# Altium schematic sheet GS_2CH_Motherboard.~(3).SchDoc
size A1; Dpartment: R&D; Date: 2024-10-27; DrawnBy: 杜龙彬; DocumentNumber: 2; Revision: V1.01; SheetNumber: 3; SheetTotal: 3; Model: 型号; Size: A1; Department: R&D
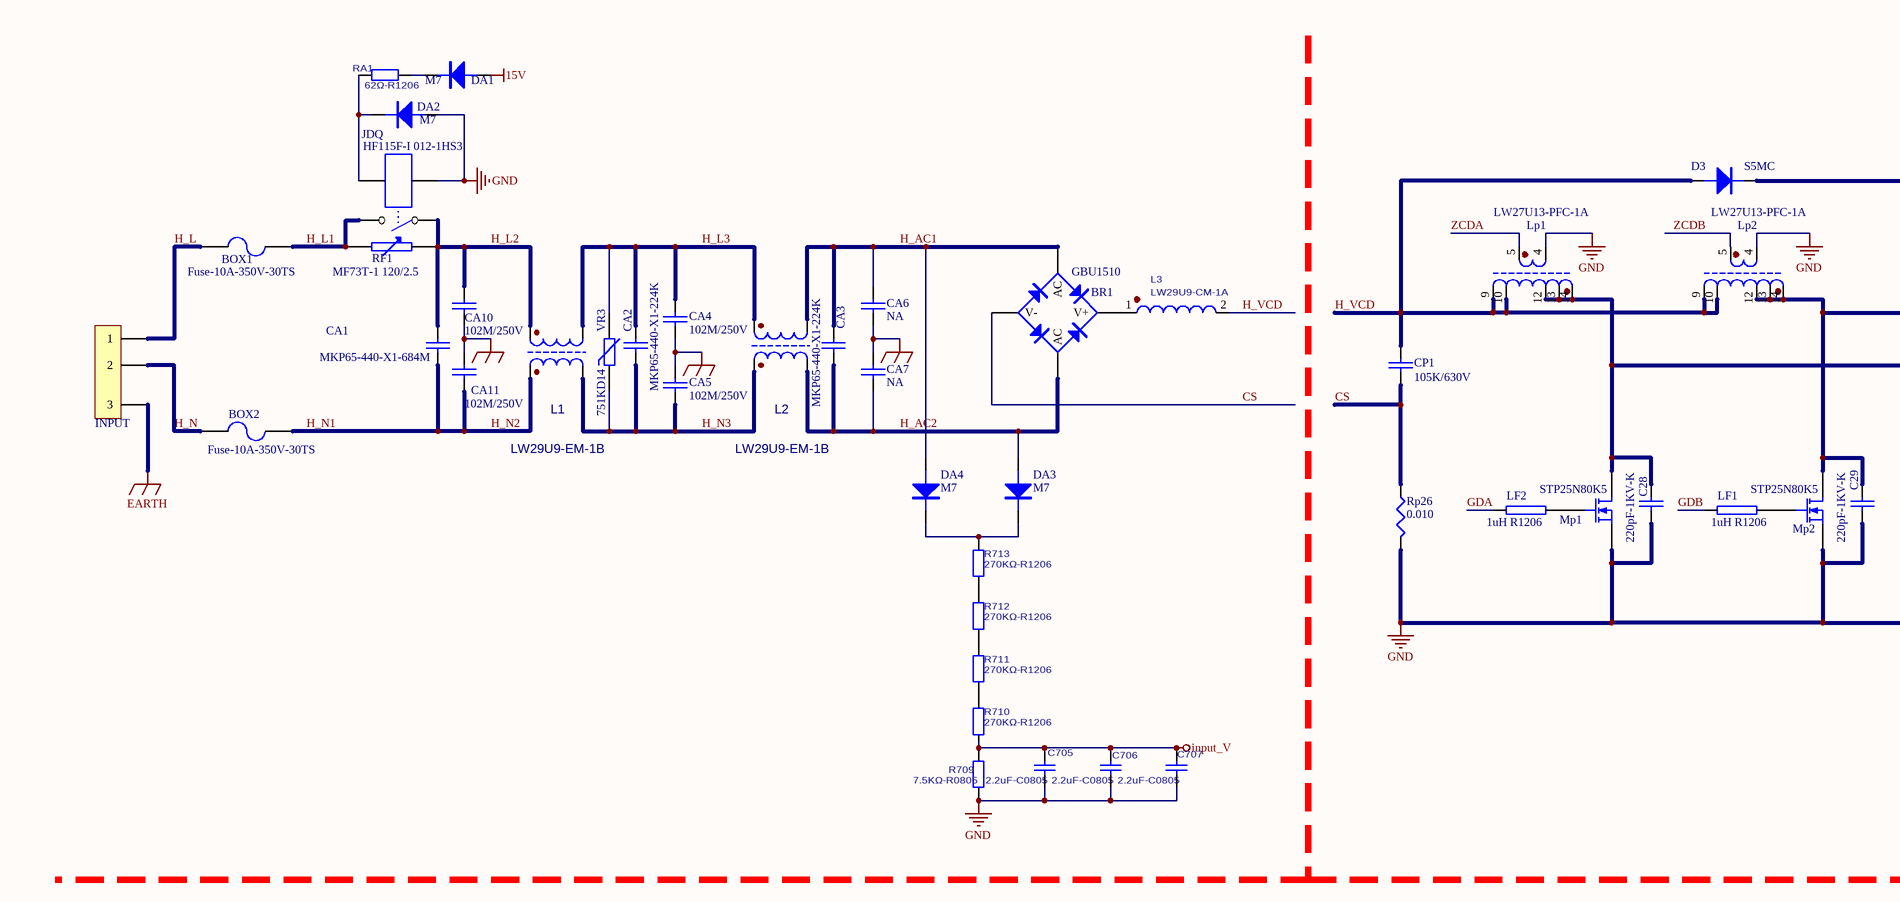
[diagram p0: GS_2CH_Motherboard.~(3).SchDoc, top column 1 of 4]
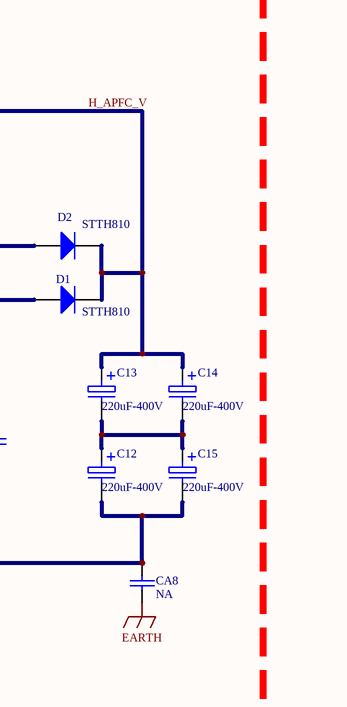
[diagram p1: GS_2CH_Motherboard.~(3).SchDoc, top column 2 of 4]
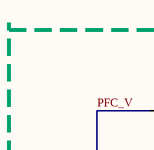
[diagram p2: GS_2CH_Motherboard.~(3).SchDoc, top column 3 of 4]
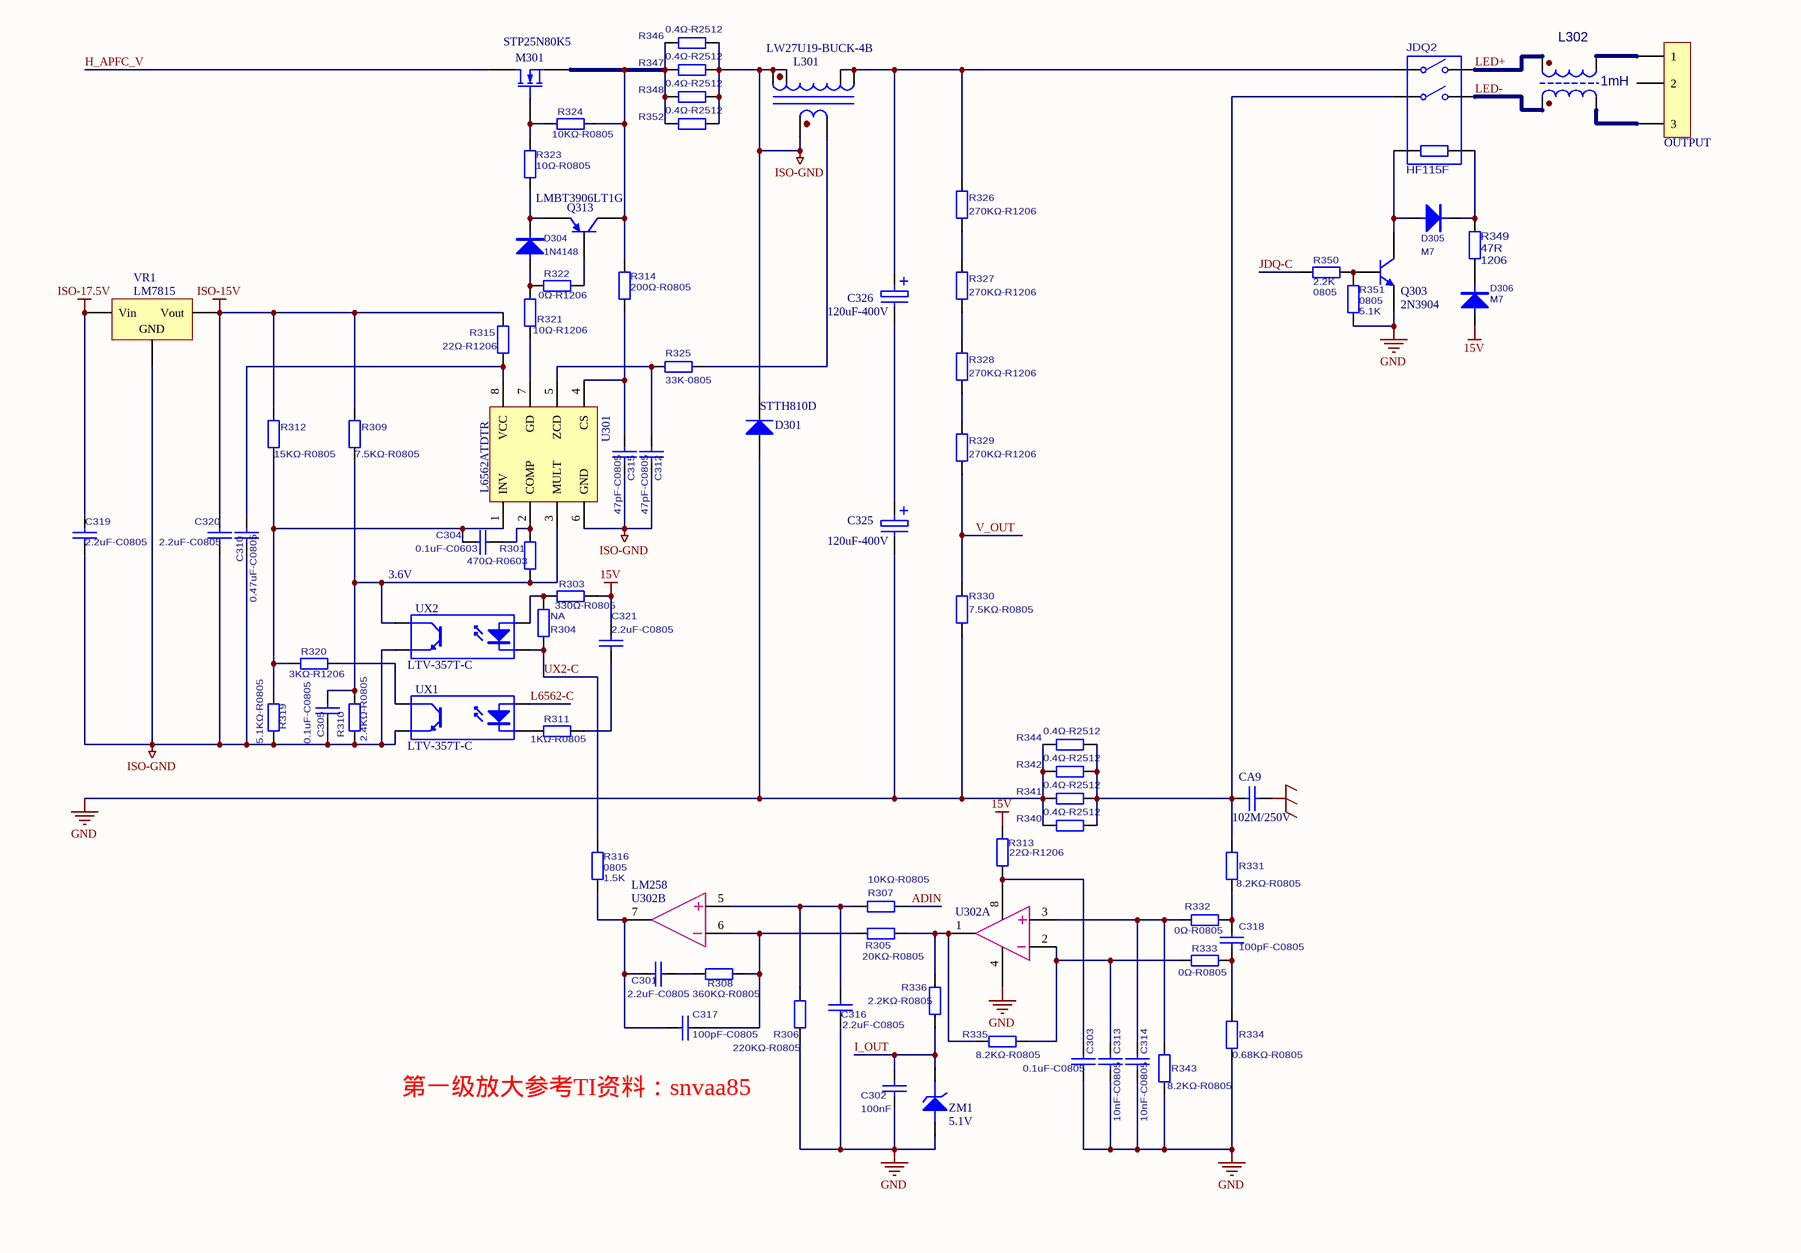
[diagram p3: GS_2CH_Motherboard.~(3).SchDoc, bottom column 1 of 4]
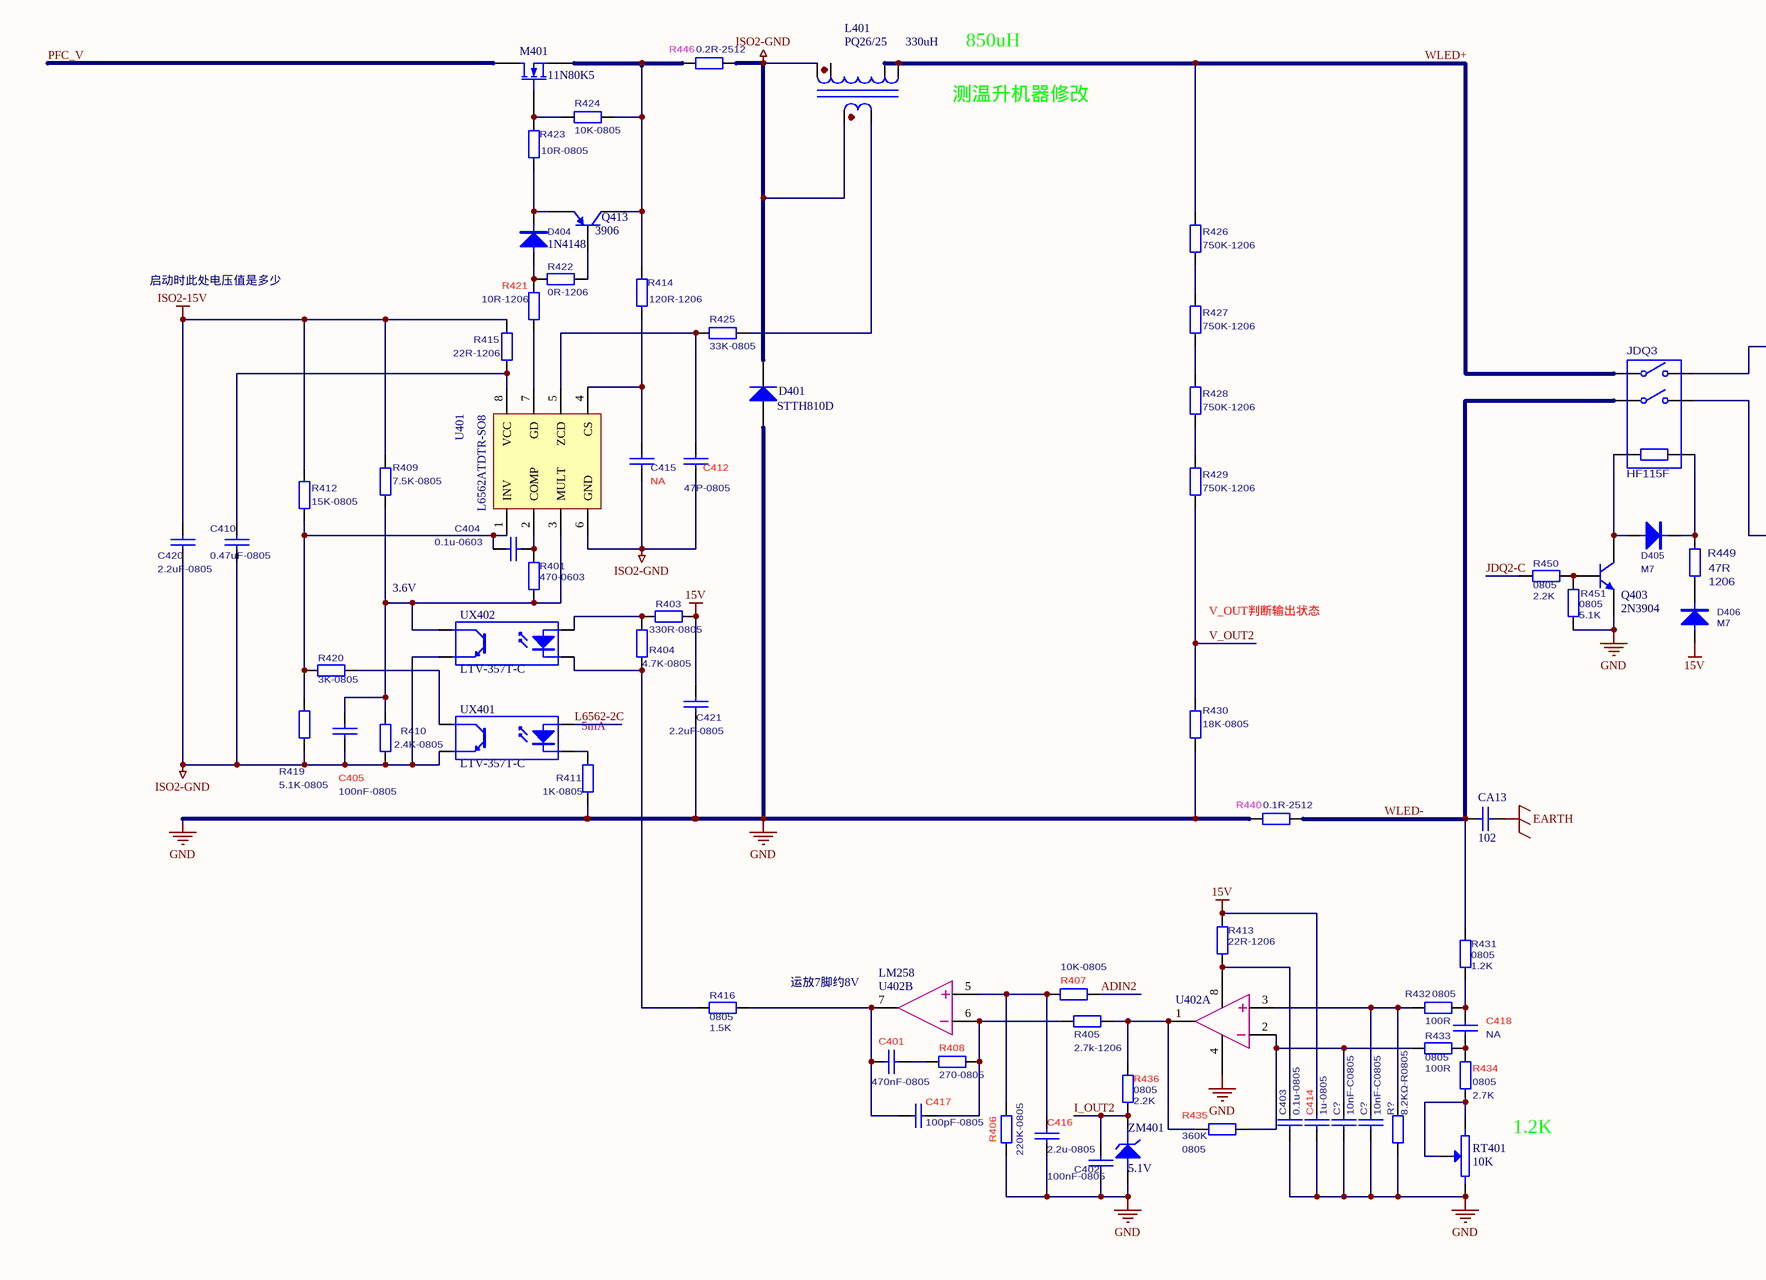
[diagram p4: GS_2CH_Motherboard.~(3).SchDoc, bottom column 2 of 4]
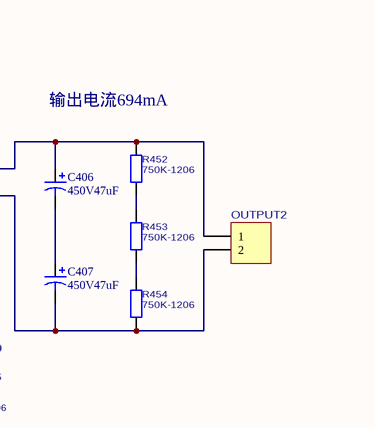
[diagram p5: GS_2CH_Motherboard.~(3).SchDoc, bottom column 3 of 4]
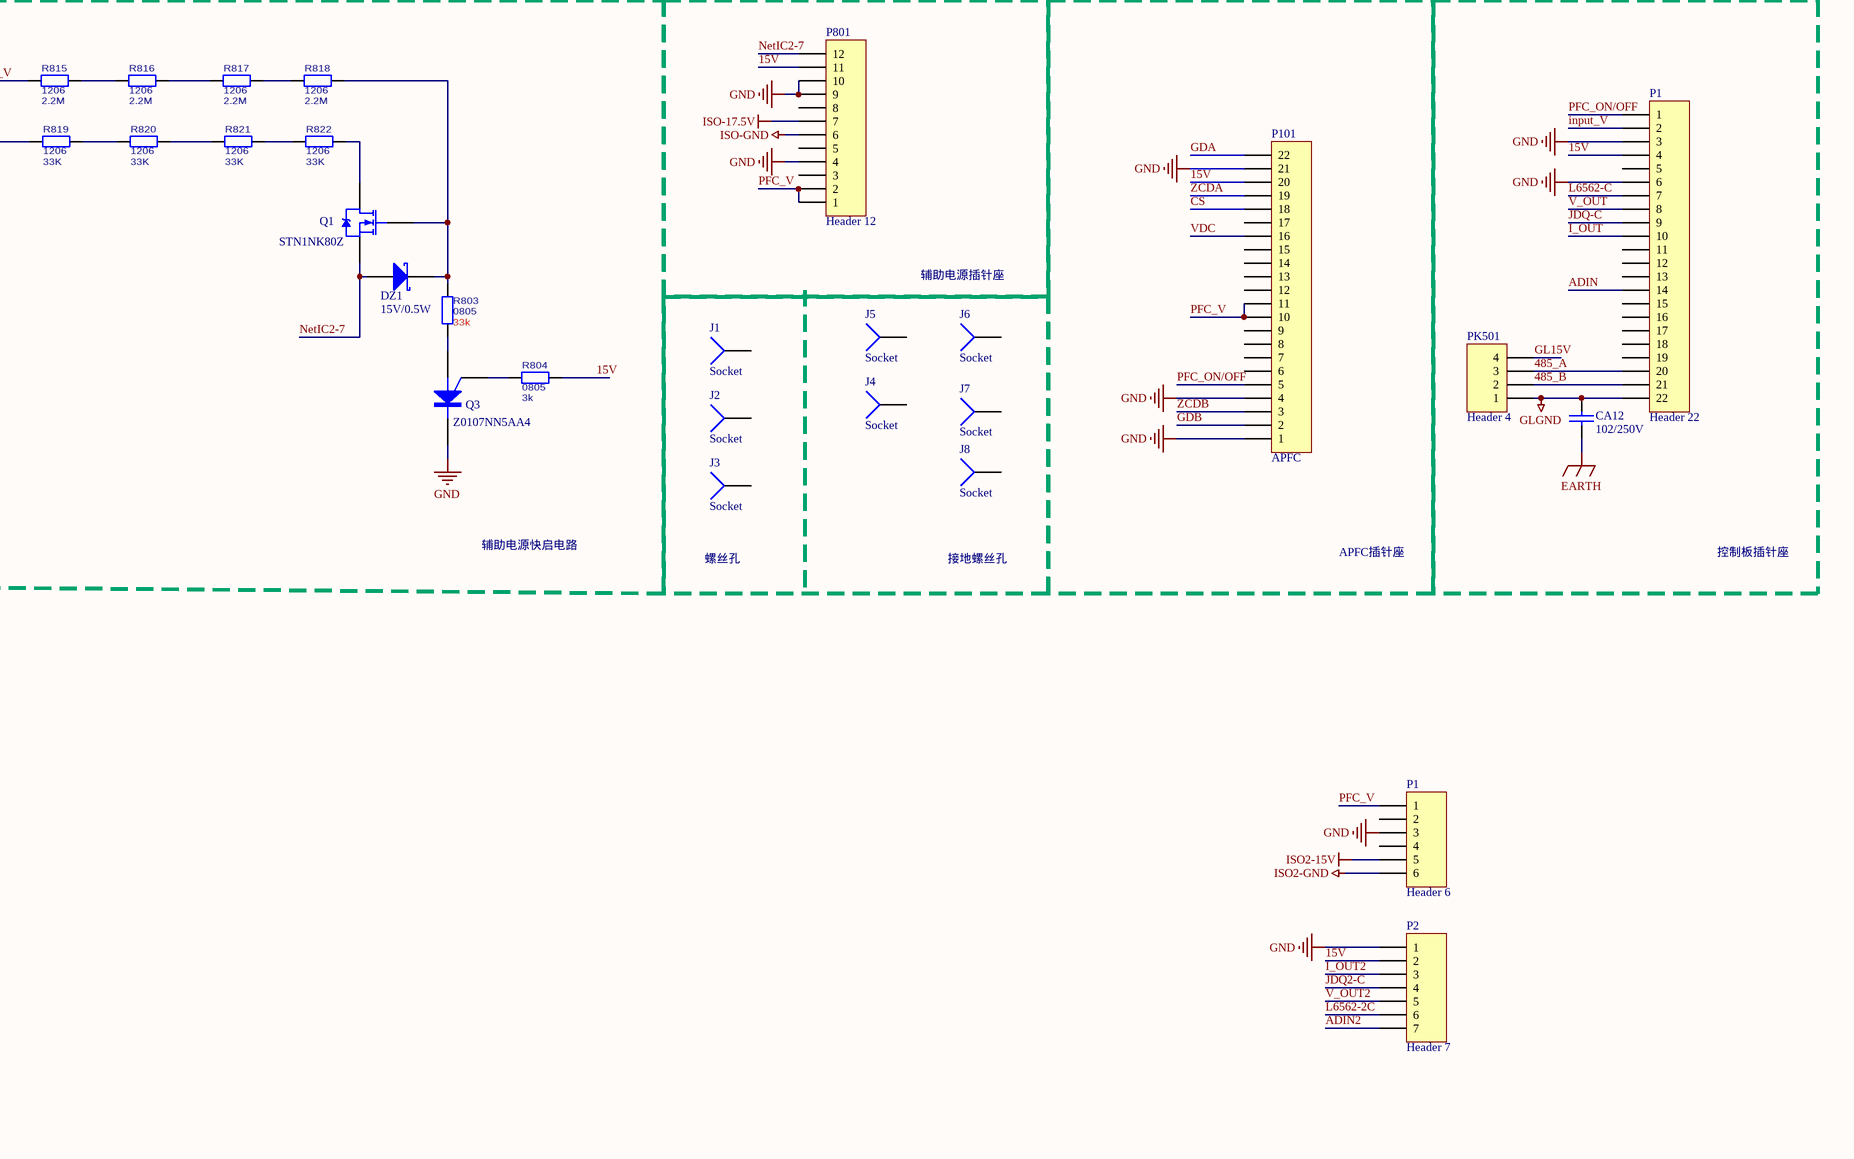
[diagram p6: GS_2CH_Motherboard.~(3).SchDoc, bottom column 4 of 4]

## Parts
(Parts that share a designator on the sheet are numbered #1, #2 ... from top to bottom, then left to right.)
BOX1  Fuse-10A-350V-30TS  [10A保险]
BOX2  Fuse-10A-350V-30TS  [10A保险]
BR1  GBU1510  [BRIDGE-TK]
C12  220uF-400V  [C250V/120uF]
C13  220uF-400V  [C250V/120uF]
C14  220uF-400V  [C250V/120uF]
C15  220uF-400V  [C250V/120uF]
C28  220pF-1KV-K  [Y2C]
C29  220pF-1KV-K  [Y2C]
C301  2.2uF-C0805  [RW0805]
C302  value 100nF  [RW0805]  (hidden comment: 0805)
C303  0.1uF-C0805  [RW0805]
C304  value 0.1uF-C0603  [RW0603]
C305  value 0.1uF-C0805  [RW0805]  (hidden comment: 301008)
C310  0.47uF-C0805  [RW0805]
C312  47pF-C0805  [RW0805]
C313  10nF-C0805  [RW0805]
C314  10nF-C0805  [RW0805]
C315  47pF-C0805  [RW0805]
C316  2.2uF-C0805  [RW0805]
C317  100pF-C0805  [RW0805]
C318  100pF-C0805  [RW0805]
C319  2.2uF-C0805  [RW0805]
C320  2.2uF-C0805  [RW0805]
C321  2.2uF-C0805  [RW0805]
C325  120uF-400V  [C250V/120uF]
C326  120uF-400V  [C250V/120uF]
C401  value 470nF-0805  [RW0805]
C402  value 100nF-0805  [RW0805]  (hidden comment: 0805)
C403  value 0.1u-0805  [RW0805]  (hidden comment: 301008)
C404  value 0.1u-0603  [RW0603]
C405  value 100nF-0805  [RW0805]  (hidden comment: 301008)
C406  450V47uF  [CE12.5]
C407  450V47uF  [CE12.5]
C410  value 0.47uF-0805  [RW0805]  (hidden comment: 301009)
C412  301001  [RW0805]  (value not drawn)
C414  value 1u-0805  [RW0805]  (hidden comment: 301008)
C415  (no value)  [RW0805]
C416  value 2.2u-0805  [RW0805]  (hidden comment: 301008)
C417  value 100pF-0805  [RW0805]  (hidden comment: 301008)
C418  value NA  [RW0805]  (hidden comment: 0805)
C420  value 2.2uF-0805  [RW0805]  (hidden comment: 301013)
C421  value 2.2uF-0805  [RW0805]  (hidden comment: 301013)
C705  2.2uF-C0805  [RW0805]
C706  2.2uF-C0805  [RW0805]
C707  2.2uF-C0805  [RW0805]
C?#1  10nF-C0805  [RW0805]
C?#2  10nF-C0805  [RW0805]
CA1  MKP65-440-X1-684M  [2.2uF/400V]
CA2  MKP65-440-X1-224K  [X2C-B 22-27]
CA3  MKP65-440-X1-224K  [X2C-B 22-27]
CA4  102M/250V  [Y2C]
CA5  102M/250V  [Y2C]
CA6  NA  [Y2C]
CA7  NA  [Y2C]
CA8  NA  [Y2C]
CA9  102M/250V  [Y2C]
CA10  102M/250V  [Y2C]
CA11  102M/250V  [Y2C]
CA12  102/250V  [Y2C]
CA13  102  [Y2C]
CP1  105K/630V  [2.2UF/630VRCD]
D1  STTH810  [U880]
D2  STTH810  [U880]
D3  S5MC  [D-SMC]
D301  STTH810D  [U880]
D304  1N4148  [SOD-123]
D305  M7  [SMA]
D306  M7  [SMA]
D401  value STTH810D  [TO-220-KA]  (hidden comment: 308006)
D404  value 1N4148  [SOD-123]  (hidden comment: 307004)
D405  M7  [SMA]
D406  M7  [SMA]
DA1  M7  [M7]
DA2  M7  [M7]
DA3  M7  [M7]
DA4  M7  [M7]
DZ1  15V/0.5W  [SOD-123]
INPUT  INPUT  [INPUT-JST-6P]  (value not drawn)
J1  Socket  [螺丝孔]
J2  Socket  [螺丝孔]
J3  Socket  [螺丝孔]
J4  Socket  [接地标志]
J5  Socket  [接地标志]
J6  Socket  [接地标志]
J7  Socket  [接地标志]
J8  Socket  [接地标志]
JDQ  HF115F-I 012-1HS3  [RELAY-HF115F - 3]
JDQ2  HF115F  [RELAY-HF115F]
JDQ3  HF115F  [RELAY-HF115F]
L1  LW29U9-EM-1B  [L-EMC]
L2  LW29U9-EM-1B  [L-EMC]
L3  LW29U9-CM-1A  [差模电感27*27*15，P=12]
L301  LW27U19-BUCK-4B  [EE42/20]
L302  1mH  [B-CM22X12]
L401  PQ26/25  value 330uH  [T-PQ2625]
LF1  1uH R1206  [RW1206]
LF2  1uH R1206  [RW1206]
Lp1  LW27U13-PFC-1A  [W1U15-PF-5A]
Lp2  LW27U13-PFC-1A  [W1U15-PF-5A]
M301  STP25N80K5  [TO220-3]
M401  value 11N80K5  [TO220VS]  (hidden comment: 314012)
Mp1  STP25N80K5  [TO220-3]
Mp2  STP25N80K5  [TO220-3]
OUTPUT  INPUT  [INPUT-JST-6P]  (value not drawn)
OUTPUT2  322055  [JST-3.96-2P]  (value not drawn)
P1#1  Header 22  [HDR1X22]
P1#2  Header 6  [6P插座]
P2  Header 7  [2.0*7]
P101  APFC  [金手指-APFC]
P801  Header 12  [HDR1X12]
PK501  Header 4  [4针插座]
Q1  STN1NK80Z  [SOT-223-NPN]
Q3  Z0107NN5AA4  [SOT-223-NPN]
Q303  2N3904  [SOT-23-BEC]
Q313  LMBT3906LT1G  [SOT-23-BEC]
Q403  2N3904  [SOT-23-BEC]
Q413  value 3906  [SOT-23-BEC]  (hidden comment: 309005)
R301  470Ω-R0603  [RW0603]
R303  330Ω-R0805  [RW0805]
R304  NA  [RW0805]
R305  20KΩ-R0805  [RW0805]
R306  220KΩ-R0805  [RW0805]
R307  10KΩ-R0805  [RW0805]
R308  360KΩ-R0805  [RW0805]
R309  7.5KΩ-R0805  [RW0805]
R310  2.4KΩ-R0805  [RW0805]
R311  1KΩ-R0805  [RW0805]
R312  15KΩ-R0805  [RW0805]
R313  22Ω-R1206  [RW1206]
R314  200Ω-R0805  [RW0805]
R315  22Ω-R1206  [RW1206]
R316  0805  value 1.5K  [RW0805]
R319  5.1KΩ-R0805  [RW0805]
R320  3KΩ-R1206  [RW1206]
R321  10Ω-R1206  [RW1206]
R322  0Ω-R1206  [RW1206]
R323  10Ω-R0805  [RW0805]
R324  10KΩ-R0805  [RW0805]
R325  value 33K-0805  [RW0805]  (hidden comment: 303055)
R326  270KΩ-R1206  [RW1206]
R327  270KΩ-R1206  [RW1206]
R328  270KΩ-R1206  [RW1206]
R329  270KΩ-R1206  [RW1206]
R330  7.5KΩ-R0805  [RW0805]
R331  8.2KΩ-R0805  [RW0805]
R332  0Ω-R0805  [RW0805]
R333  0Ω-R0805  [RW0805]
R334  0.68KΩ-R0805  [RW0805]
R335  8.2KΩ-R0805  [RW0805]
R336  2.2KΩ-R0805  [RW0805]
R340  0.4Ω-R2512  [RW2512]
R341  0.4Ω-R2512  [RW2512]
R342  0.4Ω-R2512  [RW2512]
R343  8.2KΩ-R0805  [RW0805]
R344  0.4Ω-R2512  [RW2512]
R346  0.4Ω-R2512  [RW2512]
R347  0.4Ω-R2512  [RW2512]
R348  0.4Ω-R2512  [RW2512]
R349  1206  value 47R  [RW1206]
R350  0805  value 2.2K  [RW0805]
R351  0805  value 5.1K  [RW0805]
R352  0.4Ω-R2512  [RW2512]
R401  value 470-0603  [RW0603]
R403  value 330R-0805  [RW0805]
R404  value 4.7K-0805  [RW0805]
R405  value 2.7k-1206  [RW1206]
R406  value 220K-0805  [RW0805]
R407  value 10K-0805  [RW0805]  (hidden comment: 303020)
R408  value 270-0805  [RW0805]  (hidden comment: 303046)
R409  value 7.5K-0805  [RW0805]
R410  value 2.4K-0805  [RW0805]
R411  value 1K-0805  [RW0805]
R412  value 15K-0805  [RW0805]  (hidden comment: 303053)
R413  value 22R-1206  [RW1206]  (hidden comment: 303074)
R414  value 120R-1206  [RW1206]
R415  value 22R-1206  [RW1206]  (hidden comment: 303074)
R416  0805  value 1.5K  [RW0805]
R419  value 5.1K-0805  [RW0805]
R420  value 3K-0805  [RW0805]
R421  value 10R-1206  [RW1206]  (hidden comment: 303075)
R422  value 0R-1206  [RW1206]
R423  value 10R-0805  [RW0805]  (hidden comment: 303073)
R424  value 10K-0805  [RW0805]  (hidden comment: 303043)
R425  value 33K-0805  [RW0805]  (hidden comment: 303055)
R426  value 750K-1206  [RW1206]  (hidden comment: 303094)
R427  value 750K-1206  [RW1206]  (hidden comment: 303094)
R428  value 750K-1206  [RW1206]  (hidden comment: 303094)
R429  value 750K-1206  [RW1206]  (hidden comment: 303094)
R430  value 18K-0805  [RW0805]  (hidden comment: 303033)
R431  0805  value 1.2K  [RW0805]
R432  0805  value 100R  [RW0805]
R433  0805  value 100R  [RW0805]
R434  0805  value 2.7K  [RW0805]
R435  0805  value 360K  [RW0805]
R436  0805  value 2.2K  [RW0805]
R440  value 0.1R-2512  [RW2512]
R446  value 0.2R-2512  [RW2512]
R449  1206  value 47R  [RW1206]
R450  0805  value 2.2K  [RW0805]
R451  0805  value 5.1K  [RW0805]
R452  value 750K-1206  [RW1206]  (hidden comment: 303094)
R453  value 750K-1206  [RW1206]  (hidden comment: 303094)
R454  value 750K-1206  [RW1206]  (hidden comment: 303094)
R709  7.5KΩ-R0805  [RW0805]
R710  270KΩ-R1206  [RW1206]
R711  270KΩ-R1206  [RW1206]
R712  270KΩ-R1206  [RW1206]
R713  270KΩ-R1206  [RW1206]
R803  0805  value 33k  [RW0805]
R804  0805  value 3k  [RW0805]
R815  1206  value 2.2M  [RW1206]
R816  1206  value 2.2M  [RW1206]
R817  1206  value 2.2M  [RW1206]
R818  1206  value 2.2M  [RW1206]
R819  1206  value 33K  [RW1206]
R820  1206  value 33K  [RW1206]
R821  1206  value 33K  [RW1206]
R822  1206  value 33K  [RW1206]
R?  8.2KΩ-R0805  [RW0805]
RA1  62Ω-R1206  [RW1206]
RF1  MF73T-1 120/2.5  [热敏]
Rp26  0.010  [康铜丝]
RT401  10K  [直插电位器]
U301  L6562ATDTR  [SO-8]
U302  311026  [SOP-8]  (value not drawn)  (parts A,B of 2)
U401  value L6562ATDTR-SO8  [SO-8]  (hidden comment: 311046)
U402  311026  [SOP-8]  (value not drawn)  (parts A,B of 2)
UX1  LTV-357T-C  [LTV]
UX2  LTV-357T-C  [LTV]
UX401  value LTV-357T-C  [LTV]  (hidden comment: 317001)
UX402  value LTV-357T-C  [LTV]  (hidden comment: 317001)
VR1  LM7815  [78M05]
VR3  751KD14  [YAMIN-7.62]
ZM1  5.1V  [二极管]
ZM401  5.1V  [二极管]

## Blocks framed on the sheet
辅助电源插针座: P801
APFC插针座: P101
控制板插针座: CA12 P1#1 PK501

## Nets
15V: C321.1 C414.2 C421.1 D306.A D406.A DA1.1(A) P1#1.4 P2.2 P101.20 P801.11 R303.1 R313.2 R403.1 R413.2 R804.1
EARTH: CA4.2 CA5.1 CA6.2 CA7.1 CA8.2 CA9.2 CA10.2 CA11.1 CA12.2 CA13.2 INPUT.3
GLGND: CA12.1 P1#1.22 PK501.1
GND: C12.2 C15.2 C28.2 C29.2 C302.2 C303.2 C313.2 C314.2 C316.2 C325.2 C402.2 C403.2 C414.1 C416.2 C421.2 C705.1 C706.1 C707.1 C?#1.2 C?#2.2 CA8.1 D301.1 D401.1 DA2.1(A) JDQ.3 Lp1.4 Lp2.4 Mp1.3 Mp2.3 P1#1.3 P1#1.6 P1#2.3 P2.1 P101.1 P101.4 P101.21 P801.4 P801.9 P801.10 Q3.B(K) Q303.E Q403.E R306.1 R330.1 R334.2 R340.1 R341.1 R342.1 R343.2 R344.1 R351.1 R406.1 R411.1 R430.1 R440.1 R451.1 R709.1 R?.2 Rp26.2 RT401.3 U302.4(U-) U402.4(U-) ZM1.1(A) ZM401.1(A)
input_V: C705.2 C706.2 C707.2 P1#1.2 R709.2 R710.2
ISO2-15V: C420.1 P1#2.5 R409.2 R412.1 R415.2
ISO2-GND: C405.1 C410.2 C412.2 C415.2 C420.2 D401.3 L401.5 L401.8 P1#2.6 R410.1 R419.1 R446.2 U401.6(GND) UX401.3(E) UX402.3(E)
ISO-15V: C320.1 R309.2 R312.1 R315.2 VR1.3(Vout)
ISO-17.5V: C319.1 P801.7 VR1.1(Vin)
ISO-GND: C305.1 C310.2 C312.2 C315.2 C319.2 C320.2 D301.2 L301.6 L301.7 L301.8 P801.6 R310.1 R319.1 R346.2 R347.2 R348.2 R352.2 U301.6(GND) UX1.3(E) UX2.3(E) VR1.2(GND)
485_A: P1#1.20 PK501.3
485_B: P1#1.21 PK501.2
ADIN: P1#1.14 R307.2
ADIN2: P2.7 R407.2
CS: BR1.1(V-) CP1.2 P101.18 Rp26.1
GDA: LF2.1 P101.22
GDB: LF1.1 P101.2
GL15V: PK501.4
H_AC1: BR1.3(AC) CA3.1 CA6.1 DA4.1(A) L2.4
H_AC2: BR1.2(AC) CA3.2 CA7.2 DA3.1(A) L2.2
H_APFC_V: C13.1 C14.1 D1.2(K) D2.2 D3.2(K) M301.2
H_L: BOX1.1 INPUT.1
H_L1: BOX1.2 JDQ.1 RF1.1
H_L2: CA1.1 CA10.1 JDQ.2 L1.3 RF1.2
H_L3: CA2.1 CA4.1 L1.4 L2.3 VR3.1
H_N: BOX2.2 INPUT.2
H_N1: BOX2.1 CA1.2 CA11.2 L1.1  [also labelled H_N2]
H_N3: CA2.2 CA5.2 L1.2 L2.1 VR3.2
H_VCD: CP1.1 D3.1(A) L3.2 Lp1.9 Lp1.10 Lp2.9 Lp2.10
I_OUT: C302.1 P1#1.10 R336.2 ZM1.2(K)
I_OUT2: C402.1 P2.3 R436.2 ZM401.2(K)
JDQ2-C: P2.4 R450.1
JDQ-C: P1#1.9 R350.1
L6562-2C: P2.6 UX401.1(A)
L6562-C: P1#1.7 UX1.1(A)
LED+: JDQ2.3 L302.3
LED-: JDQ2.4 L302.1
NetIC2-7: DZ1.1(A) P801.12 Q1.E
PFC_ON/OFF: P1#1.1 P101.5
PFC_V: M401.2 P1#2.1 P101.10 P101.11 P801.1 P801.2 R815.1 R819.1
UX2-C: R304.2 R316.1 UX2.2(K)
V_OUT: P1#1.8 R329.2 R330.2
V_OUT2: P2.5 R429.2 R430.2
VDC: P101.16
WLED+: JDQ3.6 L401.10 L401.11 R426.1
WLED-: CA13.1 JDQ3.5 R431.1 R440.2
ZCDA: Lp1.5 P101.19
ZCDB: Lp2.5 P101.3
NetBR1_4: BR1.4(V+) L3.1
NetC12_1: C12.1 C13.2 C14.2 C15.1
NetC28_1: C28.1 D1.1(A) Lp1.12 Lp1.13 Lp1.14 Mp1.2
NetC29_1: C29.1 D2.1 Lp2.12 Lp2.13 Lp2.14 Mp2.2
NetC301_1: C301.1 R308.1
NetC301_2: C301.2 C317.2 R316.2 U302.7
NetC303_1: C303.1 R313.1 U302.8(U+)
NetC304_1: C304.1 R301.1 U301.2(COMP)
NetC304_2: C304.2 R312.2 R319.2 R320.2 U301.1(INV)
NetC305_2: C305.2 R301.2 R309.1 R310.2 U301.3(MULT) UX2.4(C)
NetC310_1: C310.1 R315.1 U301.8(VCC)
NetC312_1: C312.1 R325.1 U301.5(ZCD)
NetC313_1: C313.1 R333.1 R335.1 U302.2
NetC314_1: C314.1 R332.2 R343.1 U302.3
NetC315_1: C315.1 R314.1 U301.4(CS)
NetC316_1: C316.1 R306.2 R307.1 U302.5
NetC317_1: C317.1 R305.1 R308.2 U302.6
NetC318_1: C318.1 R331.2 R332.1
NetC318_2: C318.2 R333.2 R334.1
NetC321_2: C321.2 R311.1
NetC325_1: C325.1 C326.2
NetC326_1: C326.1 JDQ2.5 L301.10 L301.11 R326.1
NetC401_1: C401.1 R408.1
NetC401_2: C401.2 C417.2 R416.2 U402.7
NetC403_1: C403.1 R413.1 U402.8(U+)
NetC404_1: C404.1 R401.1 U401.2(COMP)
NetC404_2: C404.2 R412.2 R419.2 R420.2 U401.1(INV)
NetC405_2: C405.2 R401.2 R409.1 R410.2 U401.3(MULT) UX402.4(C)
NetC406_+: C406.+ JDQ3.4 OUTPUT2.1 R452.2
NetC406_-: C406.- C407.+
NetC407_-: C407.- JDQ3.3 OUTPUT2.2 R454.1
NetC410_1: C410.1 R415.1 U401.8(VCC)
NetC412_1: C412.1 R425.1 U401.5(ZCD)
NetC415_1: C415.1 R414.1 U401.4(CS)
NetC416_1: C416.1 R406.2 R407.1 U402.5
NetC417_1: C417.1 R405.1 R408.2 U402.6
NetC418_1: C418.1 R431.2 R432.1
NetC418_2: C418.2 R433.2 R434.1
NetC?#1_1: C?#1.1 R433.1 R435.1 U402.2
NetC?#2_1: C?#2.1 R432.2 R?.1 U402.3
NetCA9_1: CA9.1 JDQ2.6 R331.1 R340.2 R341.2 R342.2 R344.2
NetD304_A: D304.A R321.1 R322.1
NetD304_K: D304.K Q313.E R323.1
NetD305_A: D305.A JDQ2.1 Q303.C
NetD305_K: D305.K JDQ2.2 R349.2
NetD306_K: D306.K R349.1
NetD404_A: D404.A R421.1 R422.1
NetD404_K: D404.K Q413.E R423.1
NetD405_A: D405.A JDQ3.1 Q403.C
NetD405_K: D405.K JDQ3.2 R449.2
NetD406_K: D406.K R449.1
NetDA1_2: DA1.2(K) RA1.2
NetDA2_2: DA2.2(K) JDQ.4 RA1.1
NetDA3_2: DA3.2(K) DA4.2(K) R713.1
NetDZ1_2: DZ1.2(K) Q1.B R803.1 R818.2
NetL301_4: L301.4 R325.2
NetL302_2: L302.2 OUTPUT.3
NetL302_4: L302.4 OUTPUT.1
NetL401_2: L401.2 R425.2
NetLF1_2: LF1.2 Mp2.1
NetLF2_2: LF2.2 Mp1.1
NetM301_1: M301.1 R323.2 R324.2
NetM301_3: M301.3 Q313.C R314.2 R324.1 R346.1 R347.1 R348.1 R352.1
NetM401_1: M401.1 R423.2 R424.2
NetM401_3: M401.3 Q413.C R414.2 R424.1 R446.1
NetQ1_C: Q1.C R822.2
NetQ3_C: Q3.C(A) R803.2
NetQ3_E: Q3.E(G) R804.2
NetQ303_B: Q303.B R350.2 R351.2
NetQ313_B: Q313.B R322.2
NetQ403_B: Q403.B R450.2 R451.2
NetQ413_B: Q413.B R422.2
NetR303_2: R303.2 R304.1 UX2.1(A)
NetR305_2: R305.2 R335.2 R336.1 U302.1
NetR311_2: R311.2 UX1.2(K)
NetR320_1: R320.1 UX1.4(C)
NetR321_2: R321.2 U301.7(GD)
NetR326_2: R326.2 R327.1
NetR327_2: R327.2 R328.1
NetR328_2: R328.2 R329.1
NetR403_2: R403.2 R404.1 UX402.1(A)
NetR404_2: R404.2 R416.1 UX402.2(K)
NetR405_2: R405.2 R435.2 R436.1 U402.1
NetR411_2: R411.2 UX401.2(K)
NetR420_1: R420.1 UX401.4(C)
NetR421_2: R421.2 U401.7(GD)
NetR426_2: R426.2 R427.1
NetR427_2: R427.2 R428.1
NetR428_2: R428.2 R429.1
NetR434_2: R434.2 RT401.1 RT401.2
NetR452_1: R452.1 R453.2
NetR453_1: R453.1 R454.2
NetR710_1: R710.1 R711.2
NetR711_1: R711.1 R712.2
NetR712_1: R712.1 R713.2
NetR815_2: R815.2 R816.1
NetR816_2: R816.2 R817.1
NetR817_2: R817.2 R818.1
NetR819_2: R819.2 R820.1
NetR820_2: R820.2 R821.1
NetR821_2: R821.2 R822.1

Not connected (* = marked no-connect by the designer): J1 1; J2 1; J3 1; J4 1; J5 1; J6 1; J7 1; J8 1; L401 9; OUTPUT 2; P1#1 5 11 12 13 15 16 17 18 19; P1#2 2 4; P101 6 7 8 9 12 13 14 15 17; P801 3 5 8

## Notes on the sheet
- 测温升机器修改
- 850uH
- 启动时此处电压值是多少
- 输出电流694mA
- (near UX2) 3.6V
- 辅助电源快启电路
- 螺丝孔
- 接地螺丝孔
- (near UX402) 3.6V
- V_OUT判断输出状态
- 5mA
- 第一级放大参考TI资料：snvaa85
- 运放7脚约8V
- 1.2K

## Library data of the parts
BOX1 BOX2 = FUSE2: Fuse
BR1 = BRIEGR
C12-C15 C325 C326 = 直插电解电容: 直插电容
C28 C29 C302 C318 C402 C418 = C
C301 C303-C305 C313 C314 C316 C317 C401 C403-C405 C414 C416 C417 C?#1 C?#2 = CAP: 贴片电容
C310 C312 C315 C319-C321 C410 C412 C415 C420 C421 = C: 贴片电容
C406 C407 = Cap Pol2: Polarized Capacitor (Axial); Value: 2.2uF 275VAC
C705-C707 = Cap: 贴片电容
CA1-CA13 CP1 = CAP: Capacitor
D1 D2 = Diode 1N914: High Conductance Fast Diode; pin to pad: 1>3 2>1
D3 DA1-DA4 = DIO: pin to pad: 1>A 2>K
D301 = Diode 1N914: 直插二极管; pin to pad: 1>3 2>1
D304 D404 = DIO: 贴片二极管
D305 D306 D405 D406 = DIO
D401 = Diode 1N914: 直插二极管; pin to pad: 1>A 3>K
DZ1 = D Schottky: Schottky Diode; pin to pad: 1>A 2>K
INPUT OUTPUT = CON6: Connector
JDQ = RELAY-SPST
JDQ2 JDQ3 = Relay - 两组常开: Dual-Pole Single-Throw Relay
L1 L2 L302 = L1
L3 = 差模电感
L301 L401 = inductance2
LF1 LF2 = RES
Lp1 Lp2 = L-PFC-33262
M301 = MOSFET-N: TO220mos管; pin to pad: 1>G 2>D 3>S; PackageDocument: 1995/1996
M401 = MOSFET-N: TO220mos管; PackageDocument: 1995/1996
Mp1 Mp2 = MOSFET-N: N-Channel MOSFET; pin to pad: 1>G 2>D 3>S; PackageDocument: 1995/1996
OUTPUT2 = Header 2: 接线端子
P1#1 P101 = Header 22: Header, 22-Pin
P1#2 = Header 6: Header, 6-Pin
P2 = Header 7: Header, 7-Pin
P801 = Header 12: Header, 12-Pin
PK501 = Header 4: Header, 4-Pin
Q1 = NMOS-2: N-Channel Power MOSFET; Note: Pin 2 is electrically connected to pin 4.
Q3 = PUT: Programmable Unijunction Transistor
Q303 Q403 = NPN: NPN Bipolar Transistor
Q313 Q413 = PNP: 贴片三极管
R301 R303-R315 R319-R330 R340-R342 R344 R346-R348 R352 R401 R403-R415 R419-R430 R440 R446 R452-R454 R709-R713 RA1 = Res2: 贴片电阻
R316 R331-R336 R343 R349-R351 R416 R431-R436 R449-R451 R803 R804 R815-R822 R? = Res2: Resistor
RF1 = RES4
Rp26 = RES1
RT401 = POT2
U301 U401 = L6562: 贴片集成电路
U302 U402 = LM393: 贴片集成电路
UX1 UX2 UX401 UX402 = Optoisolator1: 贴片光耦
VR1 = Volt Reg: Voltage Regulator
VR3 = VARISTOR
ZM1 ZM401 = 稳压管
